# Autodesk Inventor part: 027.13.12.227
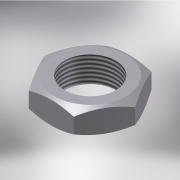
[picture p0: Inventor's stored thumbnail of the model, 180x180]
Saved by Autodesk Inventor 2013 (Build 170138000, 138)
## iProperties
Shininess: 64.0
Length Units: 11269
Angle Units: 11279
Time Units: 11290
Mass Units: 11283
Length Display Precision: 3
Angle Display Precision: 2
Created: 2002-02
Part Number: 027.13.12.227
Material: Steel, Mild
Document SubType Name: Modeling
Designer: SOleg
Density: 7.86 g/cm^3
Density: 0.0
Volumn: 0.0
Area: 0.0
PropertySet Name: Model Information
Control State: 0
Master: False
Checked Out: True
Checked Out Date: 2008-10-15
Last Check In Date: 2008-10-15
Author: SOleg
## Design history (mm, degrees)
sketch "Sketch1" dims "d0" = 41
  geometry: L1 (11.836, 20.5)-(23.671, 0); L2 (23.671, 0)-(11.836, -20.5); L3 (11.836, -20.5)-(-11.836, -20.5); L4 (-11.836, -20.5)-(-23.671, 0); L5 (-23.671, 0)-(-11.836, 20.5); L6 (-11.836, 20.5)-(11.836, 20.5); C1 r 13.5 at (0, 0); 3 further points
  constraints: 12 end point, 1 centre point, 1 coincident, 1 midpoint, 1 vertical alignment, 14 other
  dimensions: "d3" = 27 diameter of C1
extrude "Extrusion1" new body sketch "Sketch1" distance "d1" = 13.5; taper "d2" = 0 deg
sketch "Sketch2"
  geometry: L1 (-23.671, 0)-(-23.671, 13.5) reference; L2 (-23.671, 6.75)-(22.312, 6.75); L3 (-24.386, 13.5)-(-19, 13.5); L4 (-19, 13.5)-(-24.386, 10.391); L5 (-24.386, 10.391)-(-24.386, 13.5); L6 (-11.836, 13.5)-(-23.671, 13.5) reference; L7 (11.836, 13.5)-(-11.836, 13.5) reference; L8 (0, 13.5)-(0, -0.037); L9 (-19, 13.5)-(-19, 12.078); L10 (-19, 0)-(-24.386, 3.109); L11 (-24.386, 3.109)-(-24.386, 0); L12 (-24.386, 0)-(-19, 0)
  constraints: 18 end point, 3 perpendicular, 3 symmetric about line, 2 midpoint, 2 parallel, 1 collinear, 3 other
  dimensions: "d4" = 38 diameter of L9 L8; "d5" = 30 deg angle of L4 L3
revolve "Revolution1" sketch "Sketch2" stored, may be unused: angle "d6" = 90 deg
thread "Thread1" dims "d7" = 10, "d8" = 0
body "Solid1"
